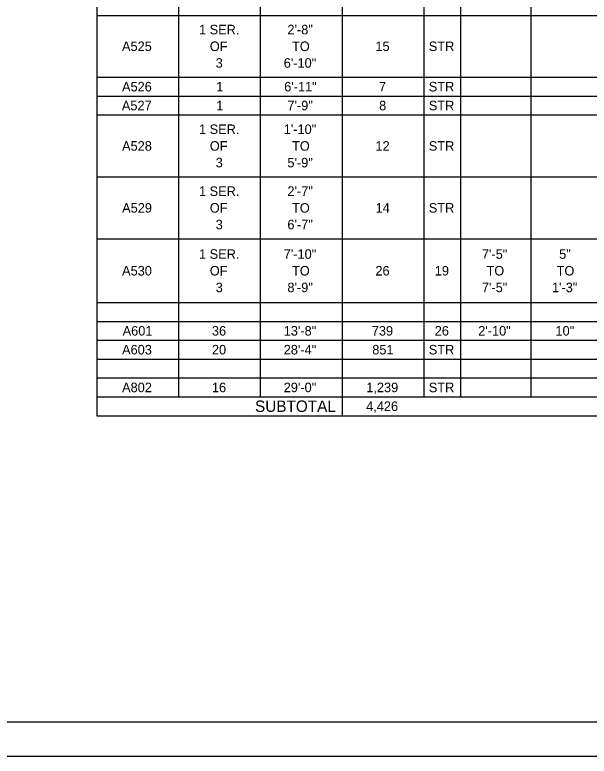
# Model space of a CAD drawing. Extents: x 0 to 34, y 0 to 22.
# Drawn here: x 17 to 25.42, y 0 to 10.88 of the extents above; entities that cross this region are included whole.
import ezdxf

# ---------------------------------------------------------------- set-up
doc = ezdxf.new("R2010")
doc.units = 0
for name, color, linetype in [('Default', 7, 'Continuous'), ('SH_Border', 7, 'Continuous'), ('SH_Cut_Line', 7, 'Continuous')]:
    doc.layers.add(name, color=color, linetype=linetype)

msp = doc.modelspace()

# ---------------------------------------------------------------- linework, layer by layer
at = {"layer": 'Default'}
for p, q in [((18.202, 19.176), (18.202, 6.105)), ((19.401, 19.176), (19.401, 6.105)), ((20.6, 19.176), (20.6, 6.105)), ((21.8, 19.176), (21.8, 6.105)), ((22.999, 19.176), (22.999, 6.105)), ((23.539, 19.176), (23.539, 6.105)), ((24.567, 19.176), (24.567, 6.105)), ((18.202, 10.875), (21.8, 10.875)), ((21.8, 10.875), (25.594, 10.875)), ((18.202, 9.966), (21.8, 9.966)), ((21.8, 9.966), (25.594, 9.966)), ((18.202, 9.689), (21.8, 9.689)), ((21.8, 9.689), (25.594, 9.689)), ((18.202, 9.413), (21.8, 9.413)), ((21.8, 9.413), (25.594, 9.413)), ((18.202, 8.503), (21.8, 8.503)), ((21.8, 8.503), (25.594, 8.503)), ((18.202, 7.594), (21.8, 7.594)), ((21.8, 7.594), (25.594, 7.594)), ((18.202, 6.659), (21.8, 6.659)), ((21.8, 6.659), (25.594, 6.659)), ((18.202, 6.382), (21.8, 6.382)), ((21.8, 6.382), (25.594, 6.382)), ((18.202, 6.105), (21.8, 6.105)), ((18.202, 6.105), (18.202, 5.829)), ((19.401, 6.105), (19.401, 5.829)), ((20.6, 6.105), (20.6, 5.829)), ((21.8, 6.105), (25.594, 6.105)), ((21.8, 6.105), (21.8, 5.829)), ((22.999, 6.105), (22.999, 5.829)), ((23.539, 6.105), (23.539, 5.829)), ((24.567, 6.105), (24.567, 5.829)), ((18.202, 5.829), (21.8, 5.829)), ((18.202, 5.829), (18.202, 4.998)), ((19.401, 5.829), (19.401, 5.275)), ((20.6, 5.829), (20.6, 5.275)), ((21.8, 5.829), (25.594, 5.829)), ((21.8, 5.829), (21.8, 4.998)), ((22.999, 5.829), (22.999, 5.275)), ((23.539, 5.829), (23.539, 5.275)), ((24.567, 5.829), (24.567, 5.275)), ((18.202, 5.552), (21.8, 5.552)), ((21.8, 5.552), (25.594, 5.552)), ((18.202, 5.275), (21.8, 5.275)), ((21.8, 5.275), (25.594, 5.275)), ((18.202, 4.998), (21.8, 4.998)), ((21.8, 4.998), (25.594, 4.998))]:
    msp.add_line(p, q, dxfattribs=at)
at = {"layer": 'SH_Border'}
msp.add_lwpolyline([(1.5, 21.5), (33.5, 21.5), (33.5, 0.5), (1.5, 0.5)], close=True, dxfattribs=at)
at = {"layer": 'SH_Cut_Line'}
msp.add_lwpolyline([(0, 0), (34, 0), (34, 22), (0, 22)], close=True, dxfattribs=at)

# ---------------------------------------------------------------- texts
at = {"layer": 'Default'}
for s, height, p in [('1 SER.', 0.14, (19.701, 10.596)), ('2\'-8"', 0.14, (20.998, 10.596)), ('A525', 0.14, (18.572, 10.351)), ('OF', 0.14, (19.86, 10.351)), ('TO', 0.14, (21.066, 10.351)), ('15', 0.14, (22.289, 10.351)), ('STR', 0.14, (23.072, 10.351)), ('3', 0.14, (19.946, 10.106)), ('6\'-10"', 0.14, (20.944, 10.106)), ('A526', 0.14, (18.572, 9.758)), ('1', 0.14, (19.954, 9.758)), ('6\'-11"', 0.14, (20.951, 9.758)), ('7', 0.14, (22.341, 9.758)), ('STR', 0.14, (23.072, 9.758)), ('A527', 0.14, (18.57, 9.481)), ('1', 0.14, (19.954, 9.481)), ('7\'-9"', 0.14, (20.998, 9.481)), ('8', 0.14, (22.344, 9.481)), ('STR', 0.14, (23.072, 9.481)), ('1 SER.', 0.14, (19.701, 9.133)), ('1\'-10"', 0.14, (20.944, 9.133)), ('A528', 0.14, (18.573, 8.888)), ('OF', 0.14, (19.86, 8.888)), ('TO', 0.14, (21.066, 8.888)), ('12', 0.14, (22.29, 8.888)), ('STR', 0.14, (23.072, 8.888)), ('3', 0.14, (19.946, 8.643)), ('5\'-9"', 0.14, (20.998, 8.643)), ('1 SER.', 0.14, (19.701, 8.224)), ('2\'-7"', 0.14, (20.998, 8.224)), ('A529', 0.14, (18.574, 7.979)), ('OF', 0.14, (19.86, 7.979)), ('TO', 0.14, (21.066, 7.979)), ('14', 0.14, (22.292, 7.979)), ('STR', 0.14, (23.072, 7.979)), ('3', 0.14, (19.946, 7.734)), ('6\'-7"', 0.14, (20.998, 7.734)), ('1 SER.', 0.14, (19.701, 7.301)), ('7\'-10"', 0.14, (20.944, 7.301)), ('7\'-5"', 0.14, (23.851, 7.301)), ('5"', 0.14, (24.984, 7.301)), ('A530', 0.14, (18.573, 7.056)), ('OF', 0.14, (19.86, 7.056)), ('TO', 0.14, (21.066, 7.056)), ('26', 0.14, (22.289, 7.056)), ('19', 0.14, (23.16, 7.056)), ('TO', 0.14, (23.919, 7.056)), ('TO', 0.14, (24.947, 7.056)), ('3', 0.14, (19.946, 6.811)), ('8\'-9"', 0.14, (20.998, 6.811)), ('7\'-5"', 0.14, (23.851, 6.811)), ('1\'-3"', 0.14, (24.879, 6.811)), ('A601', 0.14, (18.581, 6.174)), ('36', 0.14, (19.891, 6.174)), ('13\'-8"', 0.14, (20.944, 6.174)), ('739', 0.14, (22.236, 6.174)), ('26', 0.14, (23.159, 6.174)), ('2\'-10"', 0.14, (23.797, 6.174)), ('10"', 0.14, (24.93, 6.174)), ('A603', 0.14, (18.573, 5.897)), ('20', 0.14, (19.891, 5.897)), ('28\'-4"', 0.14, (20.944, 5.897)), ('851', 0.14, (22.243, 5.897)), ('STR', 0.14, (23.072, 5.897)), ('A802', 0.14, (18.573, 5.343)), ('16', 0.14, (19.891, 5.343)), ('29\'-0"', 0.14, (20.944, 5.343)), ('1,239', 0.14, (22.155, 5.343)), ('STR', 0.14, (23.072, 5.343)), ('SUBTOTAL', 0.168, (20.523, 5.053)), ('4,426', 0.14, (22.153, 5.067))]:
    msp.add_text(s, height=height, dxfattribs=at).set_placement(p)

doc.saveas('drawing.dxf')
